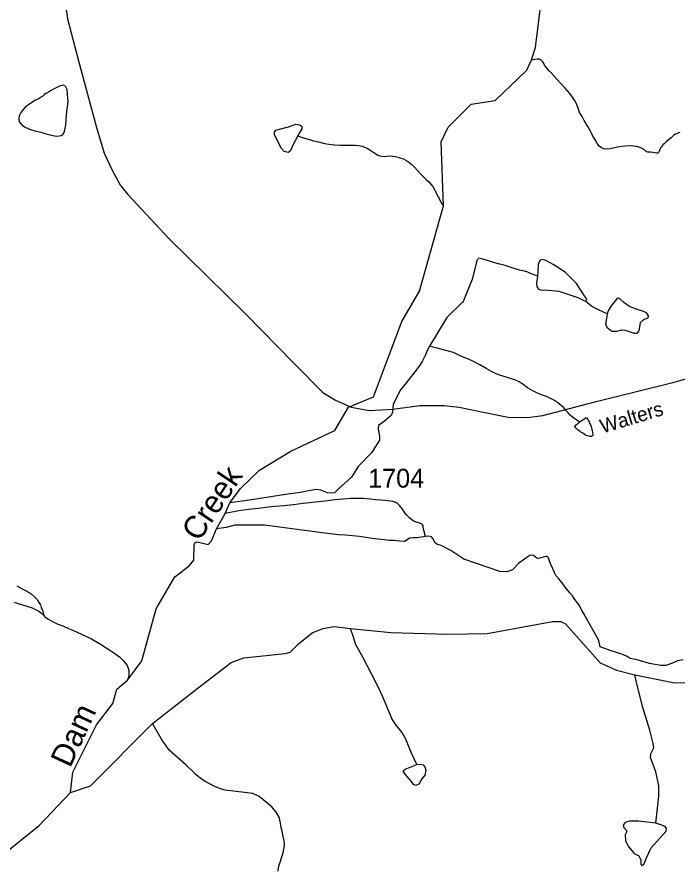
# Model space of a CAD drawing. Extents: x 2056842 to 2160602, y 826753 to 1016856.
# Drawn here: x 2109914 to 2114302, y 858411 to 864081 of the extents above; entities that cross this region are included whole.
import ezdxf

# ---------------------------------------------------------------- set-up
doc = ezdxf.new("R2010")
doc.units = 0
for name, color, linetype in [('Exist Hydrographic Creek Single Shore', 7, 'Continuous'), ('Exist Hydrographic Creek Single Shore Label', 7, 'Continuous'), ('Exist Hydrographic Misc Water Feature', 7, 'Continuous'), ('Exist Road Secondary Type 51 Attributed', 7, 'Continuous'), ('Exist Road Secondary Type 51 Label', 7, 'Continuous'), ('Exist Road Secondary Type 51 Number Label', 7, 'Continuous')]:
    doc.layers.add(name, color=color, linetype=linetype)

msp = doc.modelspace()

# ---------------------------------------------------------------- linework, layer by layer
at = {"layer": 'Exist Hydrographic Creek Single Shore'}
for points in [[(2111237.4, 860682.4), (2111295.1, 860785.5), (2111326.8, 860854.8), (2111398.1, 860951.3), (2111523.9, 861071.9), (2111731.9, 861199), (2112023.4, 861336), (2112113.9, 861489.6), (2112280, 861558.4), (2112469.8, 862059.7), (2112585.9, 862260.7), (2112745.9, 862828.5), (2112730.9, 863252), (2112776.8, 863350), (2112930, 863503.7), (2113087.9, 863526.7), (2113297.9, 863728.2), (2113329.3, 863796.1), (2113357, 863879), (2113385.8, 864111.2), (2113408.4, 864356.4), (2113408.4, 864681.8)], [(2113369.9, 862360.3), (2113346.7, 862369), (2113328.5, 862376.7), (2113306.3, 862386.1), (2113283.2, 862393.3), (2113250.6, 862401.5), (2113214.1, 862411.8), (2113187, 862420.5), (2113155.6, 862430.8), (2113120, 862440.8), (2113078.3, 862451.5), (2113043.1, 862462.1), (2113015.4, 862471.6), (2112989.3, 862478.8), (2112980.1, 862479.7), (2112968.9, 862469.3), (2112962.7, 862446.7), (2112935, 862338.6), (2112889.9, 862226.4), (2112882.5, 862206.9), (2112875.7, 862192.4), (2112871.8, 862186.6), (2112868.1, 862184.3), (2112767.1, 862085.6), (2112652.8, 861896.8)], [(2112652.8, 861896.8), (2112642.8, 861880.5), (2112634.8, 861860.2), (2112625.2, 861838.4), (2112605.5, 861798.4), (2112591.9, 861775.8), (2112571.4, 861745.1), (2112499.3, 861653.9), (2112459.2, 861604.9), (2112410.2, 861510.7), (2112406.4, 861456.6), (2112397.6, 861435.3), (2112353.7, 861397.6), (2112314.8, 861367.9), (2112311, 861345.3), (2112319.8, 861298.8), (2112321, 861271.2), (2112267, 861188.3), (2112179.1, 861096.5), (2112135.2, 861026.2), (2112047.3, 860948.8), (2112022.2, 860922.4), (2112002.1, 860919.9), (2111975.7, 860922.4), (2111930.5, 860940), (2111902.9, 860943.8), (2111848.9, 860935), (2111796.2, 860924.9), (2111697, 860911.1), (2111569.6, 860891.5), (2111457.1, 860873.4), (2111326.8, 860854.8)], [(2112624.9, 860631.7), (2112615.5, 860674.5), (2112613.3, 860682.2), (2112611, 860694.3), (2112609.6, 860702.6), (2112605.3, 860710.2), (2112598.9, 860716.1), (2112593, 860718.5), (2112586.8, 860720.3), (2112577, 860723.9), (2112563, 860728), (2112548.5, 860734.2), (2112534.7, 860743.6), (2112522, 860754.5), (2112510.7, 860765.5), (2112500.5, 860775.6), (2112488.4, 860789.6), (2112476.5, 860807.2), (2112466, 860821.4), (2112453.7, 860837), (2112442.1, 860848.5), (2112428.3, 860858), (2112409.9, 860864.4), (2112392, 860866.3), (2112357.8, 860870.3), (2112326, 860873.4), (2112295.4, 860875.6), (2112257.7, 860879.7), (2112213.8, 860883.2), (2112175.3, 860884.5), (2112127.7, 860884), (2112081.6, 860880), (2112023.7, 860875.4), (2111977.6, 860869), (2111936, 860863.9), (2111874.5, 860858.7), (2111813.6, 860850.5), (2111746.5, 860841.1), (2111688.5, 860836.5), (2111626.6, 860832.1), (2111582.3, 860827), (2111534.5, 860820.8), (2111494.5, 860815.2), (2111450.6, 860810.1), (2111416.4, 860805.9), (2111386.9, 860801.5), (2111295.1, 860785.5)], [(2112624.9, 860631.7), (2112569.6, 860622.9), (2112541.5, 860623.7), (2112519.4, 860620.4), (2112503.1, 860609.1), (2112486.8, 860599), (2112452.3, 860600.7), (2112418.1, 860604.6), (2112386.1, 860606.3), (2112351.8, 860610.3), (2112272.3, 860619.1), (2112188, 860631), (2112142.1, 860636), (2112095.5, 860640.1), (2112047.7, 860643.8), (2111995.9, 860648.7), (2111957.9, 860652.9), (2111840.1, 860669.4), (2111556.3, 860707.1), (2111429.5, 860707.1), (2111359.2, 860707.1), (2111302.7, 860692), (2111237.4, 860682.4)], [(2110837, 860151), (2110961.1, 860363.1), (2111057.8, 860437.4), (2111088, 860473.9), (2111089.2, 860574.4), (2111094.2, 860590.7), (2111108.1, 860595.8), (2111139.4, 860589.5), (2111183.4, 860579.4), (2111206, 860602), (2111237.4, 860682.4)], [(2113625, 860205.2), (2113613.3, 860221.2), (2113601, 860236.8), (2113584.8, 860256.7), (2113574.8, 860268.3), (2113560.8, 860286.7), (2113544.2, 860308.7), (2113532.3, 860324.3), (2113512, 860350.1), (2113492.1, 860371.8), (2113453.6, 860457.3), (2113443.6, 860490), (2113434.8, 860500), (2113423.5, 860500), (2113375.8, 860486.2), (2113364.5, 860488.7), (2113343.1, 860506.3), (2113321.8, 860508.8), (2113245.2, 860454.5), (2113203.8, 860410.6), (2113166.1, 860396.7), (2113118.4, 860400.5), (2112881.1, 860482.2), (2112793.2, 860538.7), (2112730.4, 860571.4), (2112701.5, 860580.2), (2112687.7, 860592.7), (2112677.6, 860616.6), (2112665.1, 860629.2), (2112645, 860634.2), (2112624.9, 860631.7)], [(2109912.3, 860304.6), (2109944.3, 860286.8), (2109978.4, 860269.1), (2110008.5, 860251.1), (2110032.5, 860229.2), (2110046.8, 860213.3), (2110058.7, 860193.2), (2110068.8, 860179), (2110074.7, 860159.5), (2110084.8, 860135.3), (2110090.7, 860107.2)], [(2109892.6, 860196.8), (2109944.5, 860180.9), (2110014.8, 860157.2), (2110040.9, 860145.1), (2110058.7, 860135.2), (2110076.8, 860123.5), (2110090.7, 860107.2)], [(2114336.4, 859812.8), (2114298.7, 859805.2), (2114266, 859791.4), (2114222.1, 859775.1), (2114188.2, 859775.1), (2114112.9, 859787.6), (2114031.2, 859812.8), (2113984.8, 859822.8), (2113965.9, 859835.4), (2113929.5, 859850.5), (2113851.7, 859875.6), (2113786.4, 859898.2), (2113775.9, 859942.1), (2113674, 860123.5), (2113661.9, 860145.2), (2113652.1, 860165), (2113641.8, 860183.5), (2113625, 860205.2)], [(2110577.2, 859618.1), (2110648.1, 859677.1), (2110741.8, 859805.6), (2110837, 860151)], [(2110090.7, 860107.2), (2110096.9, 860101.3), (2110119, 860085.4), (2110149.2, 860067.5), (2110185.2, 860049.4), (2110218.9, 860037.9), (2110255, 860021.8), (2110289.2, 860008.1), (2110342.9, 859984.1), (2110407.5, 859952.5), (2110461.2, 859920.4), (2110493, 859900.5), (2110529.5, 859876.8), (2110563.8, 859854.9), (2110593.7, 859833), (2110621.8, 859805.2), (2110645.6, 859775.2), (2110651.5, 859757.2), (2110655.8, 859737.1), (2110656.3, 859711.1), (2110651.9, 859693.1), (2110648.1, 859677.1)], [(2110814.2, 859389.8), (2111115.6, 859626), (2111336.6, 859795.7), (2111419.5, 859827.1), (2111693.2, 859856), (2111727.1, 859864.8), (2111783.6, 859918.8), (2111872.8, 859991.7), (2111943.1, 860021.8), (2112018.4, 860034.4), (2112128.9, 860021.8), (2112396.4, 859994.2), (2112773.1, 859982.9), (2113034.3, 859987.9), (2113468.7, 860068.3), (2113524, 860068.3), (2113555.4, 860052), (2113786.4, 859793.2), (2113893.1, 859744.2), (2114016.2, 859714), (2114281.1, 859660), (2114427.1, 859662.3)], [(2110268, 858932.3), (2110284, 859066.6), (2110441.9, 859381.6), (2110550, 859523.7), (2110577.2, 859618.1)], [(2110268, 858932.3), (2110400.9, 858975.6), (2110814.2, 859389.8)], [(2109048.2, 857657.4), (2109136.4, 857752.7), (2109471, 858036.7), (2109603.8, 858289.8), (2109802.9, 858505.6), (2110060.9, 858713.5), (2110268, 858932.3)]]:
    msp.add_lwpolyline(points, dxfattribs=at)
at = {"layer": 'Exist Hydrographic Misc Water Feature'}
for points in [[(2113583.8, 863573.2), (2113553.2, 863609), (2113524.9, 863640.9), (2113500.9, 863665.6), (2113478.8, 863690), (2113460.3, 863709.9), (2113448.4, 863721.9), (2113436.6, 863737.5), (2113422.4, 863751.8), (2113416, 863762.1), (2113412.2, 863772), (2113406, 863783.4), (2113395.7, 863793.6), (2113385.7, 863799.5), (2113379.5, 863801.3), (2113367.7, 863801.5), (2113352.1, 863799.3), (2113339.8, 863797.2), (2113329.3, 863796.1)], [(2110090.1, 863558.7), (2110080.3, 863552.9), (2110060.4, 863540.9), (2110036.2, 863528.7), (2110018.5, 863518.8), (2109990.9, 863498.6), (2109970.8, 863484.7), (2109958.5, 863472.3), (2109938.4, 863446.5), (2109930.6, 863430.2), (2109924.8, 863410.4), (2109925, 863396.2), (2109930.8, 863382.4), (2109942.9, 863368.3), (2109962.8, 863352.3), (2109997, 863336.6), (2110031, 863326.6), (2110073.3, 863316.9), (2110099.1, 863306.9), (2110133.2, 863298.9), (2110163.1, 863293.2), (2110182.8, 863291), (2110206.8, 863295.1), (2110218.9, 863301.4), (2110225, 863309.4), (2110228.9, 863323.4), (2110236.9, 863363.2), (2110240.6, 863401.5), (2110244.7, 863453.3), (2110250.2, 863499.5), (2110252.3, 863525.2), (2110250.2, 863543.3), (2110248.2, 863569.2), (2110246.4, 863601.1), (2110237.9, 863617.4), (2110230.4, 863625), (2110222.2, 863629.1), (2110196.1, 863621.3), (2110182, 863615), (2110169.9, 863609), (2110152, 863599.2), (2110135.8, 863591.1), (2110116.4, 863579), (2110104.3, 863572.7), (2110094, 863567), (2110090.1, 863558.7)], [(2114314, 863313.7), (2114297.8, 863308.7), (2114282.2, 863301), (2114273, 863293.9), (2114256.4, 863278.5), (2114238.1, 863264.2), (2114224.8, 863252), (2114210.8, 863240.4), (2114202.6, 863232.3), (2114199.6, 863229.1), (2114192.6, 863220.1), (2114189.3, 863215.2), (2114186.6, 863210.3), (2114182.7, 863202), (2114178.8, 863194.1), (2114173.1, 863182.7), (2114169.8, 863178), (2114164.9, 863176.3), (2114158.7, 863178), (2114148.1, 863180.1), (2114134.8, 863182.1), (2114121, 863183.8), (2114103, 863184.9), (2114096, 863186.7), (2114090.9, 863189.2), (2114080, 863199.3), (2114071, 863204.4), (2114054.6, 863212.9), (2114050.7, 863214.7), (2114027.1, 863221.9), (2114007.6, 863224.5), (2113981.6, 863226), (2113950.6, 863224.2), (2113926.8, 863221.3), (2113902, 863217.8), (2113872.7, 863210.8), (2113849.3, 863205.1), (2113829.2, 863204.5), (2113809.1, 863206.6), (2113794.8, 863212.5), (2113784.7, 863218.5), (2113778.6, 863224.3), (2113770.8, 863236.1), (2113764.4, 863244.3), (2113756.6, 863258.5), (2113738, 863290.1), (2113730.2, 863305.9), (2113721.8, 863322.6), (2113711.7, 863338.3), (2113703.7, 863354.2), (2113695.3, 863368), (2113685.3, 863384.1), (2113679.3, 863393.9), (2113669.5, 863411.3), (2113661.1, 863427.9), (2113648.8, 863448.1), (2113640.8, 863469.1), (2113636.5, 863483.2), (2113630.7, 863497.5), (2113624.4, 863513.1), (2113616, 863528.9), (2113601.8, 863548.9), (2113583.8, 863573.2)], [(2111778.6, 863293.5), (2111744.7, 863229.4), (2111728.4, 863190.5), (2111714.5, 863182.9), (2111688.2, 863189.2), (2111668.1, 863210.6), (2111622.9, 863301), (2111624.1, 863316.1), (2111631.7, 863329.9), (2111656.8, 863337.5), (2111717.1, 863352.5), (2111766, 863368.9), (2111792.4, 863365.1), (2111806.2, 863352.5), (2111803.7, 863340), (2111792.4, 863316.1), (2111778.6, 863293.5)], [(2111778.6, 863293.5), (2111814.4, 863280), (2111856.6, 863268.3), (2111882.9, 863260.2), (2111915.1, 863252.1), (2111955.3, 863242.4), (2111984.8, 863236.8), (2112020.9, 863233.7), (2112057, 863231.4), (2112103.3, 863230.6), (2112130.8, 863230.4), (2112161.1, 863230.7), (2112179, 863228.9), (2112193.1, 863227.1), (2112207.5, 863223.3), (2112221.2, 863217.2), (2112239, 863209.6), (2112269.2, 863191.7), (2112283.8, 863181.3), (2112293.6, 863174.1), (2112305.7, 863165.4), (2112321.5, 863160.2), (2112338.7, 863157.5), (2112355.5, 863156.2), (2112370.7, 863157.6), (2112385.9, 863159), (2112408.2, 863158.4), (2112427.5, 863154.6), (2112443.5, 863151.1), (2112461.7, 863145), (2112479.8, 863139.1), (2112496, 863131.3), (2112515.7, 863117.7), (2112534.3, 863101.5), (2112550.3, 863085.7), (2112573.5, 863061.6), (2112592.6, 863040.8), (2112611, 863021.4), (2112631.3, 863002.9), (2112646.9, 862987.1), (2112661.3, 862971.1), (2112673.6, 862955.5), (2112687.3, 862931), (2112693.4, 862918.8), (2112700, 862907.3), (2112710.3, 862887.1), (2112716, 862875.7), (2112730.4, 862847.5), (2112736.3, 862839.3), (2112742.7, 862831.8), (2112745.9, 862828.5)], [(2113691, 862192.9), (2113696, 862201.7), (2113693.5, 862214.2), (2113677.1, 862236.8), (2113628.2, 862311), (2113599.3, 862339.9), (2113552.8, 862387.6), (2113472.5, 862437.9), (2113424.8, 862464.3), (2113398.4, 862470.5), (2113384.6, 862464.3), (2113374.5, 862439.1), (2113370.8, 862386.4), (2113369.9, 862360.3)], [(2113369.9, 862360.3), (2113363.2, 862317.3), (2113364.5, 862292.1), (2113377, 862273.3), (2113395.9, 862267), (2113419.7, 862269.5), (2113511.4, 862260.7), (2113637, 862218), (2113691, 862192.9)], [(2113832.8, 862110), (2113775.1, 862136.3), (2113731.1, 862160.2), (2113691, 862192.9)], [(2113832.8, 862110), (2113826.6, 862078.5), (2113821.5, 862042.1), (2113830.3, 862022), (2113863, 861995.6), (2113896.9, 861994.4), (2113929.5, 862003.2), (2113952.1, 862001.9), (2114012.4, 861981.8), (2114031.2, 861983.1), (2114045.1, 861996.9), (2114053.8, 862052.2), (2114075.2, 862073.5), (2114104.1, 862084.8), (2114106.6, 862097.4), (2114095.3, 862115), (2114075.2, 862125), (2114023.7, 862141.4), (2113979.8, 862159), (2113942.1, 862185.3), (2113913.2, 862211.7), (2113904.4, 862215.5), (2113893.1, 862208), (2113859.2, 862164), (2113839.1, 862130.1), (2113832.8, 862110)], [(2113647.6, 861391.4), (2113630.9, 861403.3), (2113616.6, 861412.7), (2113601.2, 861424.4), (2113586.4, 861437.2), (2113572.3, 861452.7), (2113558.4, 861468.6), (2113544, 861486.2), (2113525.8, 861502.4), (2113503.6, 861520), (2113477.8, 861537.7), (2113451.5, 861551.3), (2113429.4, 861561.6), (2113403.3, 861571.2), (2113373, 861582.3), (2113333, 861602.2), (2113302.9, 861620.1), (2113275, 861641.9), (2113248.7, 861658), (2113218.8, 861671.8), (2113196.2, 861679.7), (2113168.1, 861686.8), (2113126.3, 861700.8), (2113095.1, 861712.9), (2113064.6, 861728.5), (2113027.9, 861747.9), (2112985.8, 861771.7), (2112945.2, 861793.2), (2112911.8, 861808.5), (2112861.4, 861830.2), (2112812.8, 861854.3), (2112652.8, 861896.8)], [(2113647.6, 861391.4), (2113653.3, 861395.4), (2113661.5, 861401.1), (2113669.5, 861406.4), (2113679.1, 861413), (2113685.3, 861416.9), (2113689.2, 861419.6), (2113695.1, 861419.1), (2113703.3, 861409.3), (2113707.8, 861400.9), (2113711.7, 861393.5), (2113715.8, 861385.1), (2113721.4, 861372.9), (2113725.9, 861361.4), (2113727.5, 861353.8), (2113729.6, 861342.9), (2113732.2, 861335.6), (2113733.9, 861323.2), (2113736.5, 861313.5), (2113736.5, 861305.4), (2113733.9, 861299.6), (2113728.5, 861295.6), (2113720.3, 861295.6), (2113712.3, 861297.7), (2113698.4, 861301), (2113689, 861305.3), (2113678.3, 861311.3), (2113670.5, 861317.4), (2113658.2, 861324.9), (2113652.1, 861329.1), (2113644.1, 861335.1), (2113636.1, 861340.9), (2113632, 861344.2), (2113625.8, 861350.1), (2113619.1, 861355.9), (2113618, 861361.9), (2113625.6, 861372.4), (2113631.8, 861378.8), (2113641.6, 861386.7), (2113647.6, 861391.4)], [(2112568.4, 859117.2), (2112532, 859193.8), (2112494.3, 859285.6), (2112467.9, 859332), (2112425.3, 859387.3), (2112401.4, 859423.8), (2112339.9, 859572), (2112303.5, 859651.2), (2112269.6, 859715.3), (2112209.3, 859829.6), (2112162.8, 859912.5), (2112147.8, 859962.8), (2112128.9, 860021.8)], [(2114154.3, 858729), (2114174.4, 858908.6), (2114175.7, 858975.2), (2114155.6, 859068.2), (2114120.4, 859163.7), (2114122.9, 859187.6), (2114141.8, 859229), (2114136.7, 859257.9), (2114115.4, 859345.9), (2114068.9, 859496.6), (2114030, 859653.7), (2114016.2, 859714)], [(2111646.7, 858408.7), (2111648.3, 858419.4), (2111650.1, 858430.5), (2111651.8, 858442.8), (2111660, 858469.2), (2111669.4, 858497.4), (2111675.8, 858517.1), (2111683.4, 858543.1), (2111685.8, 858552.9), (2111688.3, 858566.8), (2111689.1, 858576.8), (2111688.9, 858591.4), (2111686.6, 858611.2), (2111683.6, 858628.3), (2111678, 858651.4), (2111673.5, 858674.5), (2111667.8, 858699.3), (2111663.9, 858727.5), (2111659.6, 858747.2), (2111655.5, 858762.8), (2111649.3, 858775.5), (2111634.2, 858801.8), (2111606.6, 858835.8), (2111522.4, 858906.1), (2111479.7, 858925), (2111423.2, 858932.5), (2111296.2, 858948.3), (2111272, 858953.6), (2111259.5, 858957.9), (2111231.6, 858969), (2111213.4, 858978.7), (2111167.7, 859002.7), (2111149.2, 859012.7), (2111119.3, 859036.4), (2111101, 859052.1), (2111083.2, 859069.9), (2111034.6, 859115.3), (2110924.7, 859212.7), (2110898.8, 859249.1), (2110879.5, 859275.5), (2110814.2, 859389.8)], [(2112568.4, 859117.2), (2112591, 859121), (2112609.8, 859115.9), (2112622.4, 859102.1), (2112627.4, 859082), (2112622.4, 859046.8), (2112601, 859021.7), (2112582.2, 858986.5), (2112560.9, 858979), (2112545.8, 858984), (2112532, 859005.4), (2112501.9, 859039.3), (2112479.2, 859068.2), (2112479.2, 859078.3), (2112490.5, 859085.8), (2112568.4, 859117.2)], [(2114154.3, 858729), (2114040, 858741.5), (2113979.8, 858741.5), (2113950.9, 858732.7), (2113938.3, 858715.2), (2113942.1, 858700.1), (2113960.9, 858680), (2113959.7, 858667.4), (2113952.1, 858649.8), (2113954.7, 858613.4), (2113972.2, 858574.4), (2114011.2, 858527.9), (2114042.6, 858510.4), (2114055.1, 858485.2), (2114055.1, 858455.1), (2114061.4, 858447.5), (2114076.5, 858453.8), (2114094, 858499.1), (2114124.2, 858564.4), (2114179.4, 858627.2), (2114223.4, 858676.2), (2114225.9, 858692.5), (2114217.1, 858706.4), (2114189.5, 858717.7), (2114154.3, 858729)]]:
    msp.add_lwpolyline(points, dxfattribs=at)
at = {"layer": 'Exist Road Secondary Type 51 Attributed'}
msp.add_lwpolyline([(2110181.9, 864524.5), (2110249.9, 864069), (2110322.7, 863790.9), (2110440.6, 863347), (2110492.3, 863176.3), (2110546, 863065.1), (2110599.7, 862963.4), (2110649.5, 862904), (2110924.5, 862609.6), (2111431.4, 862110), (2111749.5, 861785.9), (2111945, 861588.3), (2112028.4, 861537.5), (2112131.9, 861491.5), (2112254.5, 861468.5), (2112409.8, 861478.1), (2112588, 861501.1), (2112749, 861501.1), (2112848.6, 861489.6), (2113019.2, 861455.1), (2113175.4, 861425.3), (2113300, 861421.5), (2113405.4, 861434.9), (2113750.3, 861525.1), (2114276.4, 861656.4), (2114477.6, 861714)], dxfattribs=at)

# ---------------------------------------------------------------- texts
at = {"layer": 'Exist Hydrographic Creek Single Shore Label'}
for s, rotation, p in [('Creek', 56.2724, (2111121.5, 860591.4)), ('Dam', 65.2416, (2110266.6, 859090.1))]:
    msp.add_text(s, height=150, rotation=rotation, dxfattribs=at).set_placement(p)
at = {"layer": 'Exist Road Secondary Type 51 Label'}
msp.add_text('Walters', height=95, rotation=16.9573, dxfattribs=at).set_placement((2113801.2, 861314.7))
at = {"layer": 'Exist Road Secondary Type 51 Number Label'}
msp.add_text('1704', height=125, dxfattribs=at).set_placement((2112245, 860956.4))

doc.saveas('drawing.dxf')
